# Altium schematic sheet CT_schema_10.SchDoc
size 274 x 160 mm
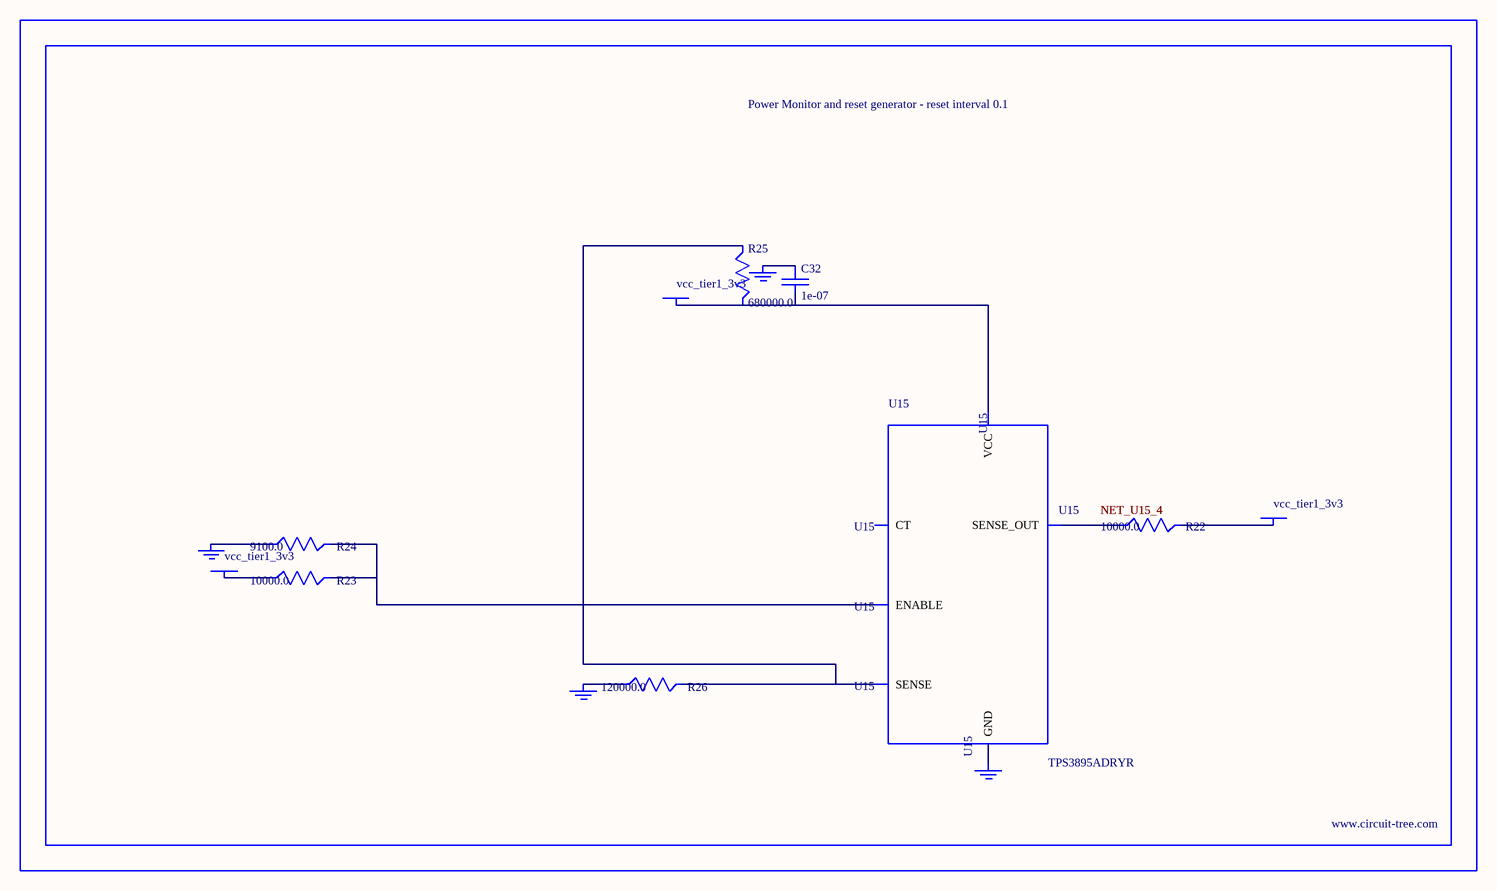
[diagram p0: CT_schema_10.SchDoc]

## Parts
BORDER9  (no value)
C32  1e-07  [C0402]
GND_INSTANCE_9_0  (no value)
GND_INSTANCE_9_1  (no value)
GND_INSTANCE_9_2  (no value)
GND_INSTANCE_9_3  (no value)
POWER_INSTANCE_9_0  vcc_tier1_3v3
POWER_INSTANCE_9_1  vcc_tier1_3v3
POWER_INSTANCE_9_2  vcc_tier1_3v3
R22  10000.0  [R0603]
R23  10000.0  [R0603]
R24  9100.0  [R0603]
R25  680000.0  [R0603]
R26  120000.0  [R0603]
U15  TPS3895ADRYR  [SON-6]

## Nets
NetC32_1: C32.1 GND_INSTANCE_9_2.0(GND)
NetC32_2: C32.2 POWER_INSTANCE_9_2.0(PWR) R25.2 U15.6(VCC)
NetGND_INSTANCE_9_0_0: GND_INSTANCE_9_0.0(GND) R24.1
NetGND_INSTANCE_9_1_0: GND_INSTANCE_9_1.0(GND) R26.1
NetGND_INSTANCE_9_3_0: GND_INSTANCE_9_3.0(GND) U15.2(GND)
NetPOWER_INSTANCE_9_0_0: POWER_INSTANCE_9_0.0(PWR) R23.1
NetPOWER_INSTANCE_9_1_0: POWER_INSTANCE_9_1.0(PWR) R22.2
NetR22_1: R22.1 U15.4(SENSE_OUT)
NetR23_2: R23.2 R24.2 U15.1(ENABLE)
NetR25_1: R25.1 R26.2 U15.3(SENSE)

Not connected (* = marked no-connect by the designer): U15 5(CT)

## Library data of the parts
BORDER9 = BORDER_PAGE9
C32 = C0402C104K3RACTU
GND_INSTANCE_9_0-GND_INSTANCE_9_3 = GND
POWER_INSTANCE_9_0-POWER_INSTANCE_9_2 = PWR
R22 R23 = RC0603JR-0710KL
R24 = RC0603JR-079K1L
R25 = RC0603JR-07680KL
R26 = RC0603JR-07120KL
